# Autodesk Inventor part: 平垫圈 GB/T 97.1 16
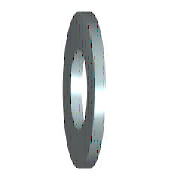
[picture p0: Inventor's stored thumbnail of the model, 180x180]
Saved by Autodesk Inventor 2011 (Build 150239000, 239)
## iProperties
Created: 2010-02
Part Number: 平垫圈 GB/T 97.1 16
Material: 低炭钢
Description: 平垫圈 - 产品等级 A
Document SubType Name: Modeling
Standard: GB/T 97.1-2002
Designer: Administrator
Standard Revision: 2002
Standards Organization: GB
Language: zh-CN
Size Designation: 16
Categories: <MemberInstance><Categories><Category DisplayName="紧固件" InternalName="e4da775c-781d-43d5-af7c-5136215cf5a6" Mnemonic="FSTN"><Category DisplayName="垫圈" InternalN
Density: 1 g/cm^3
IsCustomPart: 1
Author: Administrator
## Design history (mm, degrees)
body "Solid1"
sketch "Sketch"
  geometry: C1 r 15 at (0, 0); C2 r 8.5 at (0, 0); 1 further point
  constraints: 2 centre point, 2 coincident
  dimensions: "d0" = 17 diameter of C2 (= SD1); "d1" = 30 diameter of C1 (= SD2)
extrude "Body" new body sketch "Sketch" distance "d2" = 3 (= SD); taper "d3" = 0 deg
workaxis "Work Axis1"
workplane "Work Plane1"
other parameters: "SD1" = 17 [user parameter; used in 1 equation term], "SD2" = 30 [user parameter; used in 1 equation term], "SD" = 3 [user parameter; used in 1 equation term], "d4" = 0, "d5" = 0, "d6" = 0, "d7" = 0, "NND" = 16 [user parameter]
